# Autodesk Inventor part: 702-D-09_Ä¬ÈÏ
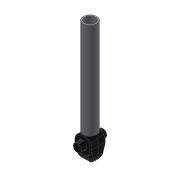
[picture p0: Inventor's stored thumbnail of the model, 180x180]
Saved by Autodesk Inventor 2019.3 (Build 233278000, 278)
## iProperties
Created: 2010-06
Part Number: 702-D-09_Ä¬ÈÏ
Material: Ogólny
Document SubType Name: Modeling
Designer: CADENGINEERING4
Density: 1 g/cm^3
Appearance: Domyślna
Author: CADENGINEERING4
Revision Number: ÈÎºÎ
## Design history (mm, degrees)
feature "NONE"
node "Bryła1"
